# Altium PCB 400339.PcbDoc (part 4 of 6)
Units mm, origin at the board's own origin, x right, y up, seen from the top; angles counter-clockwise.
Board outline 146 x 63.5 mm, 4 copper layers (Top Layer, Mid-Layer 1, Mid-Layer 2, Bottom Layer), stack 1.505 mm thick; 400 components, 261 nets, 1523 pads, 1938 vias.
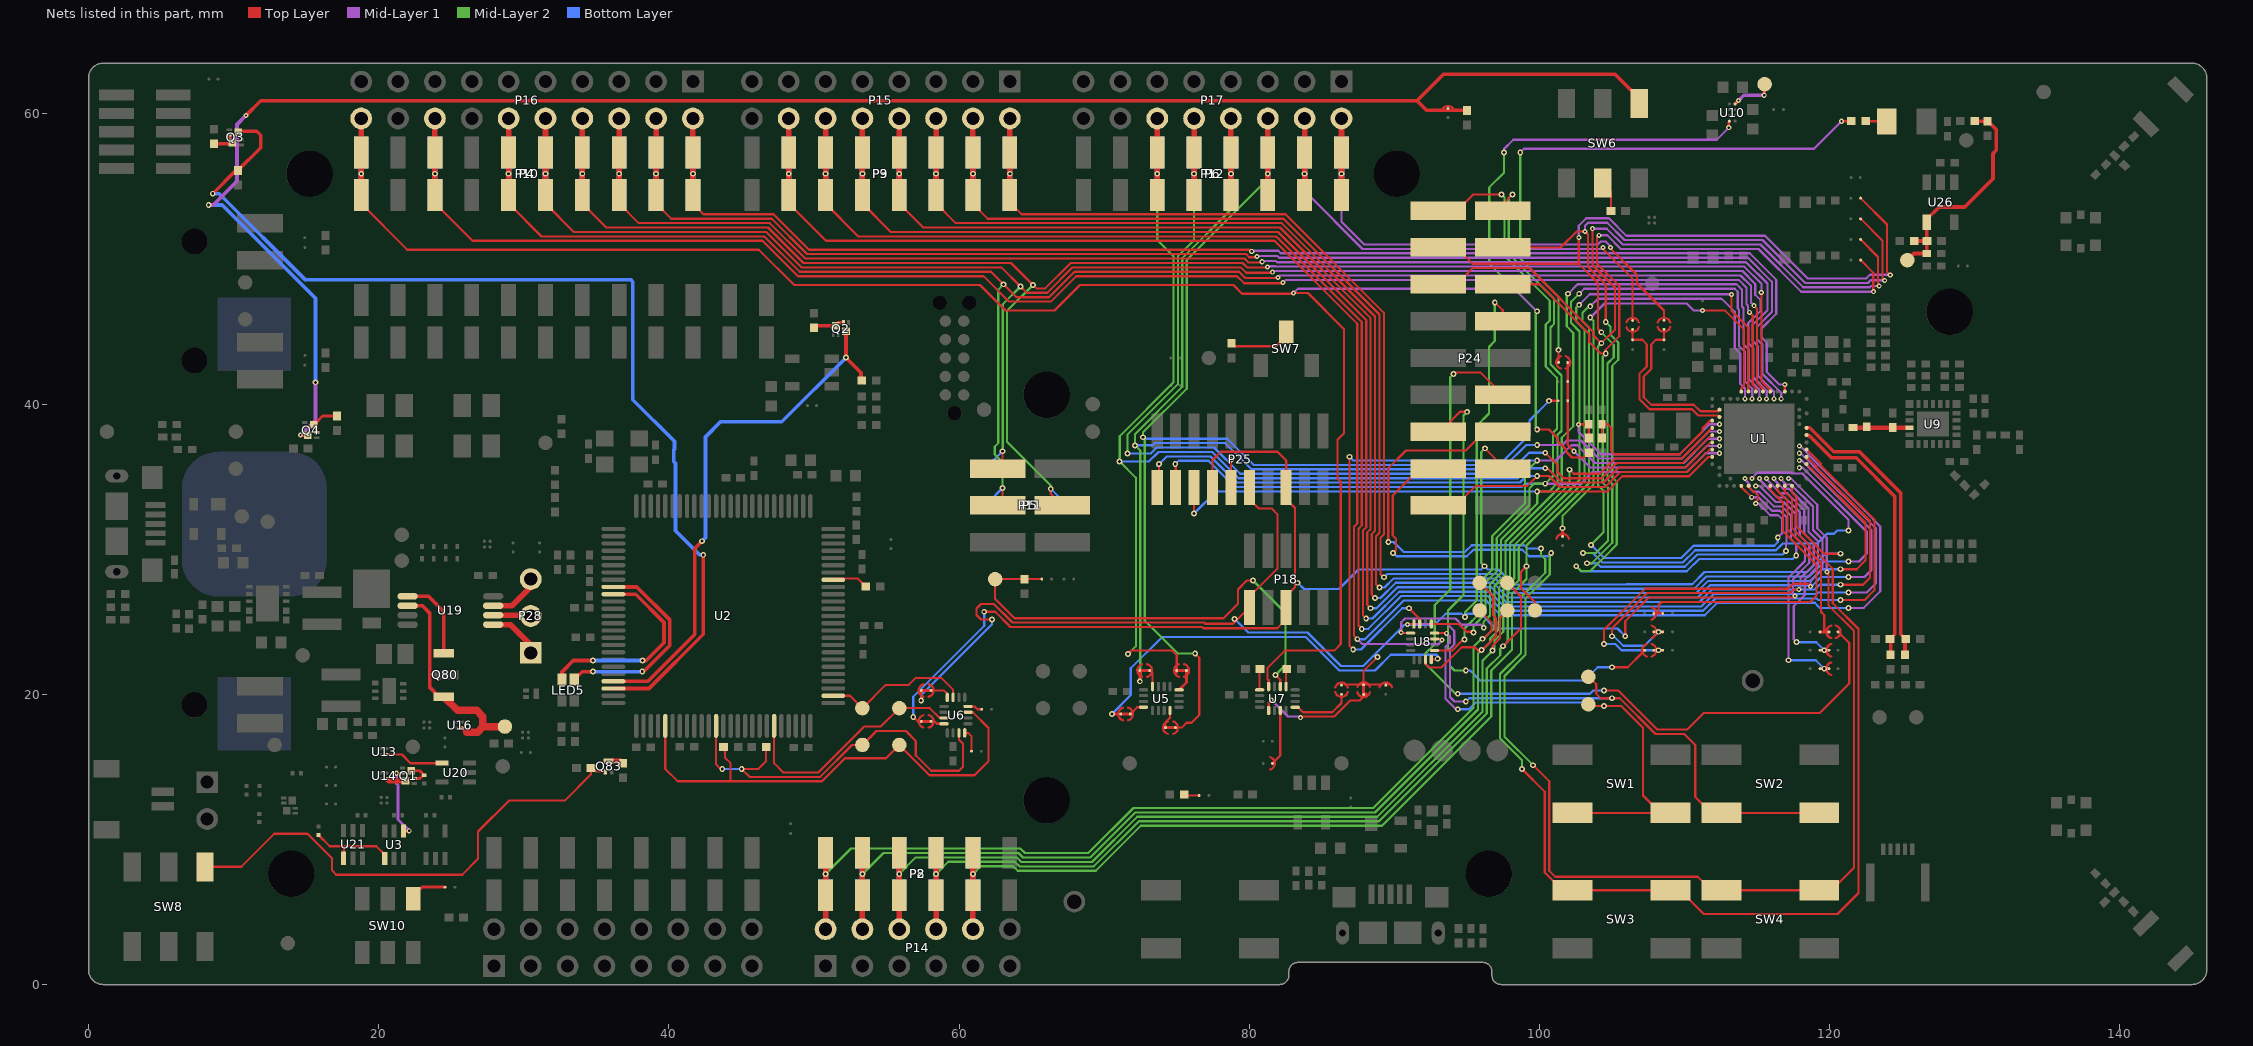
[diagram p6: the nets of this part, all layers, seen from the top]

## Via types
v1: diameter 0.4, hole 0.2, Top Layer to Bottom Layer, tented both sides, 1691 vias
v2: diameter 0.35, hole 0.15, Top Layer to Mid-Layer 1, tented both sides, 184 vias
v3: diameter 0.61, hole 0.305, Top Layer to Bottom Layer, 24 vias
v4: diameter 0.61, hole 0.305, Top Layer to Bottom Layer, tented both sides, 16 vias
v5: diameter 0.5, hole 0.3, Top Layer to Bottom Layer, tented both sides, 12 vias
v6: diameter 0.35, hole 0.15, Top Layer to Mid-Layer 1, tented top, 8 vias
v7: diameter 0.4, hole 0.2, Top Layer to Mid-Layer 1, tented top, 2 vias
v8: diameter 0.35, hole 0.15, Top Layer to Bottom Layer, tented top, 1 vias

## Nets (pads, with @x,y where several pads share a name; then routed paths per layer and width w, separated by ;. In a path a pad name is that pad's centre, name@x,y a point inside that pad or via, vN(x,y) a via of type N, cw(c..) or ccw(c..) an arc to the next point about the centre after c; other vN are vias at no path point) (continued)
NetP24_12: P24.12 SB25.2 | length 61.3
  Top Layer w0.152: v1(94.082,42.088) 94.183,42.189 95.923,42.189 P24.12@97.472,40.64 ; v1(104.445,20.269) 105.429,20.269 108.122,17.577 110.184,17.577 111.327,18.72 119.329,18.72 121.354,20.745 121.354,23.535 SB25.2@120.581,24.308
  Mid-Layer 2 w0.152: v1(94.082,42.088) 93.853,41.859 93.853,27.229 92.786,26.162 92.786,23.461 92.151,22.826 92.151,22.106 94.217,20.041 v1(94.369,20.041)
  Bottom Layer w0.152: v1(94.369,20.041) 103.484,20.041 103.712,20.269 v1(104.445,20.269)
NetP24_13: P24.13 SB20.2 | length 35.3
  Top Layer w0.152: P24.13@93.091,38.036 94.526,39.472 v1(95.021,39.472) ; v1(105.004,21.869) 106.088,21.869 107.108,22.889 SB20.2@107.257,23.038
  Mid-Layer 2 w0.152: v1(94.928,21.641) 94.148,21.641 93.836,21.953 93.836,22.938 93.701,23.073 93.701,25.782 94.767,26.849 94.767,39.218 v1(95.021,39.472)
  Bottom Layer w0.152: v1(94.928,21.641) 95.225,21.641 95.91,20.955 103.105,20.955 104.019,21.869 v1(105.004,21.869)
NetP28_1: P28.1 U19.5 | length 3.7
  Top Layer w0.381: U19.5@27.893,24.806 29.067,24.806 30.48,23.393 P28.1@30.48,22.86
NetP28_2: P28.2 U19.6 | length 2.6
  Top Layer w0.381: U19.6@27.893,25.456 30.424,25.456 P28.2@30.48,25.4
NetP28_3: P28.3 U19.7 | length 3.7
  Top Layer w0.381: U19.7@27.893,26.106 29.179,26.106 30.48,27.407 P28.3@30.48,27.94
NetQ1_2: Q1.2 U3.4 | length 5.1
  Top Layer w0.203: v2(21.227,14.561) Q1.2@21.64,14.561 ; U3.4@21.715,10.594 v6(22.102,10.594)
  Mid-Layer 1 w0.203: v2(21.227,14.561) 21.227,13.837 21.322,13.742 21.322,11.374 v6(22.102,10.594)
NetQ1_3: Q1.3 U14.A2 | length 1.2
  Top Layer w0.381: U14.A2@20.634,14.113 20.716,14.031 Q1.3@21.847,14.031
NetQ1_5: Q1.5 Q1.6 R6.2 | length 1.8
  Top Layer w0.203: Q1.6@22.247,14.731 22.822,14.731 R6.2@23.129,14.425 23.066,14.425 22.843,14.201 Q1.5@22.455,14.201
NetQ2_5: Q2.5 Q2.6 R22.2 | length 2.2
  Top Layer w0.254: R22.2@49.996,45.271 50.138,45.413 Q2.6@51.507,45.413 51.715,45.62 Q2.5@52.006,45.62
NetQ3_5: Q3.5 Q3.6 R24.2 | length 2.1
  Top Layer w0.254: R24.2@8.811,57.795 R24.2@8.661,57.945 9.831,57.945 Q3.6@9.919,58.034 9.712,58.241 Q3.5@9.712,58.5
NetQ4_3: Q4.3 R26.1 SB31.2 SW6.3 | length 130
  Top Layer w0.254: v2(10.844,59.893) 10.846,59.893 11.862,60.909 91.567,60.909 ; v2(14.617,37.867) Q4.3@15.116,37.867 ; R26.1@94.996,60.241 94.982,60.255 94.122,60.255 93.279,60.255 92.221,60.255 91.567,60.909 ; SW6.3@106.869,60.484 SW6.3@106.869,60.738 106.869,61.076 105.207,62.738 93.396,62.738 91.567,60.909
  Mid-Layer 1 w0.254: v1(8.28,53.721) 8.595,53.721 10.232,55.358 10.232,59.281 v2(10.844,59.893) ; v2(14.617,37.867) 15.646,38.896 v1(15.646,41.504)
  Bottom Layer w0.254: v1(8.28,53.721) 9.22,53.721 15.646,47.294 v1(15.646,41.504)
NetQ4_5: Q4.5 Q4.6 R41.2 | length 2.6
  Top Layer w0.152: R41.2@16.919,39.385 R41.2@17.12,39.184
  Top Layer w0.203: Q4.5@15.724,38.037 15.724,38.772 16.136,39.184 R41.2@17.12,39.184
NetQ80_1: Q80.1 U19.1 | length 5.6
  Top Layer w0.254: U19.1@22.196,26.756 23.434,26.756 24.489,25.701 Q80.1@24.489,22.836
NetQ80_3: Q80.3 TP34.1 U16.A1 U19.2 | length 15
  Top Layer w0.25: U16.A1@25.778,17.682 26.065,17.394
  Top Layer w0.254: U19.2@22.196,26.106 23.018,26.106 23.51,25.614 23.51,20.509 24.182,19.836 Q80.3@24.489,19.836
  Top Layer w0.508: Q80.3@24.489,19.836 25.427,18.898 26.746,18.898 27.178,18.466 27.178,17.755 ; 26.065,17.394 26.818,17.394 27.178,17.755 ; TP34.1@28.651,17.856 28.55,17.755 27.178,17.755
NetQ83_1: Q83.1 R94.1 SW8.4 | length 34.6
  Top Layer w0.152: SW8.4@8.028,8.109 10.522,8.109 12.802,10.389 15.088,10.389 16.789,8.687 16.789,7.851 17.071,7.569 25.756,7.569 26.851,8.664 26.851,10.544 28.981,12.675 32.817,12.675 34.638,14.495 R94.1@34.638,14.935 ; R94.1@34.714,14.961 34.988,14.687 Q83.1@35.614,14.687
NetQ83_3: Q83.3 R93.2 | length 1
  Top Layer w0.381: Q83.3@35.839,15.387 36.701,15.387 R93.2@36.83,15.257
NetR3_2: R3.2 SW6.5 | length 2.2
  Top Layer w0.152: SW6.5@104.369,55.238 104.935,54.671 R3.2@104.935,53.315
NetR4_2: R4.2 SW7.2 | length 4.4
  Top Layer w0.152: R4.2@78.791,44.188 78.985,43.994 81.84,43.994 82.55,44.704 SW7.2@82.55,44.965
NetR11_2: R11.2 R12.1 | length 1.4
  Top Layer w0.152: R11.2@122.498,59.5 123.907,59.5 R12.1@123.933,59.475
NetR18_2: R18.2 U3.1 U21.1 | length 6.2
  Top Layer w0.152: R18.2@15.85,10.307 16.627,9.53 17.603,9.53 ; U21.1@17.587,8.702 17.587,9.514 17.603,9.53 ; U3.1@20.415,8.694 20.415,8.956 19.841,9.53 17.603,9.53
NetR30_2: R30.2 U2.43 | length 2.5
  Top Layer w0.152: U2.43@51.329,27.9 51.42,27.991 53.008,27.991 R30.2@53.567,27.432
NetR49_1: R49.1 SB65.2 | length 1
  Top Layer w0.152: R49.1@75.532,13.081 75.582,13.03 SB65.2@76.548,13.03
NetR52_2: R52.2 U7.9 | length 1.2
  Top Layer w0.152: U7.9@82.54,20.535 R52.2@82.54,21.742
NetR53_2: R53.2 U7.13 | length 1.5
  Top Layer w0.152: U7.13@80.715,20.31 R53.2@80.715,21.768
NetR68_1: R68.1 SB33.2 TP19.1 U7.10 | length 33.2
  Top Layer w0.152: SB33.2@65.702,27.94 64.524,27.94 R68.1@64.516,27.932 64.508,27.94 TP19.1@62.484,27.94 62.484,26.594 63.828,25.25 78.234,25.25 79.223,26.238 79.223,27.229 79.832,27.838 v1(80.264,27.838) ; v1(81.813,21.336) 82.14,21.009 U7.10@82.14,20.535
  Mid-Layer 2 w0.152: v1(80.264,27.838) 82.499,25.604 82.499,22.021 v1(81.813,21.336)
NetSB16_2: SB16.2 U8.7 | length 36.5
  Top Layer w0.152: v1(86.919,36.371) 86.919,23.332 v1(87.163,23.088) ; v1(91.008,25.933) 91.748,25.194 U8.7@91.748,24.847 ; v1(100.672,40.231) SB16.2@101.276,40.231
  Bottom Layer w0.152: v1(86.919,36.371) 87.173,36.117 97.548,36.117 99.314,37.884 99.314,38.873 v1(100.672,40.231) ; v1(87.163,23.088) 87.705,23.088 90.551,25.933 v1(91.008,25.933)
NetSB42_1: SB42.1 U7.1 | length 8.6
  Top Layer w0.152: U7.1@81.34,18.885 81.34,19.415 v2(81.534,19.609) ; v2(83.541,18.39) 83.617,18.466 85.851,18.466 86.965,19.58 87.608,19.58 88.087,20.058
  Mid-Layer 1 w0.152: v2(81.534,19.609) 82.677,18.466 83.464,18.466 v2(83.541,18.39)
NetSB45_1: SB45.1 U7.5 | length 4.2
  Top Layer w0.152: U7.5@83.165,19.11 83.361,19.11 83.701,18.771 85.725,18.771 86.36,19.406 86.36,19.833 SB45.1@86.36,20.008
NetSB46_1: SB46.1 U7.3 | length 3.9
  Top Layer w0.152: SB46.1@81.592,15.24 81.741,15.389 82.14,15.788 U7.3@82.14,18.885
NetSB50_1: SB50.1 U8.16 | length 28.9
  Top Layer w0.152: U8.16@92.548,22.397 v1@92.907,22.397 ; v1@93.04,22.53 v1@92.907,22.397 ; v1@93.167,22.479 93.085,22.397 v1@92.907,22.397
  Top Layer w0.203: v1(70.536,18.644) 70.963,18.644 SB50.1@71.138,18.644
  Bottom Layer w0.152: v1(70.536,18.644) 71.839,19.947 71.839,21.794 73.998,23.952 83.887,23.952 86.199,21.641 88.664,21.641 89.756,22.733 92.913,22.733 v1@93.167,22.479
  other v1: 92.989,22.454
NetSB50_2: SB50.2 U5.16 | length 1.1
  Top Layer w0.152: SB50.2@71.813,18.644 72.28,19.11 U5.16@72.714,19.11
NetSB51_2: SB51.2 U5.4 | length 1.3
  Top Layer w0.152: SB51.2@74.237,17.704 74.237,18.077 74.539,18.38 U5.4@74.539,18.885
NetSB52_2: SB52.2 U5.8 | length 1.6
  Top Layer w0.152: U5.8@75.157,20.307 U5.8@75.164,20.314
  Top Layer w0.203: U5.8@75.164,20.31 75.164,20.314 75.674,20.824 SB52.2@75.674,21.641
NetSB53_2: SB53.2 U5.12 | length 1.2
  Top Layer w0.152: SB53.2@73.134,21.641 73.332,21.443 U5.12@73.332,20.532
NetSB54_2: SB54.2 U6.16 | length 1.6
  Top Layer w0.152: U6.16@60.392,17.342 60.628,17.342 60.851,17.119 SB54.2@60.851,16.078
NetSB55_2: SB55.2 U6.4 | length 1
  Top Layer w0.152: U6.4@60.617,19.167 61.071,19.167 61.265,18.974 SB55.2@61.562,18.974
NetSB56_2: SB56.2 U6.8 | length 1.5
  Top Layer w0.152: SB56.2@58.072,20.269 58.953,20.269 59.192,20.031 U6.8@59.192,19.792
NetSB57_2: SB57.2 U6.12 | length 1
  Top Layer w0.152: SB57.2@58.072,18.136 58.318,18.136 58.487,17.967 U6.12@58.967,17.967 U6.12@58.967,17.937
NetSB58_2: SB58.2 SW10.1 | length 2.6
  Top Layer w0.203: SW10.1@22.375,5.914 22.375,6.093 22.987,6.706 SB58.2@24.58,6.706
NetSW1_2: SW1.2 TP20.1 U8.4 | length 35.3
  Top Layer w0.152: U8.4@92.773,24.222 93.609,24.222 v2@93.624,24.206 ; SW1.2@102.278,11.83 SW1.2@108.331,11.83 ; TP20.1@103.378,19.304 103.48,19.202 v1(104.445,19.202) 105.634,19.202 107.137,17.699 107.137,13.024 SW1.2@108.331,11.83 ; SW1.2@109.707,11.83 SW1.2@109.028,11.83 SW1.2@108.331,11.83
  Mid-Layer 1 w0.152: v2@93.624,24.206 93.828,24.003 93.828,23.562 93.531,23.266 93.531,19.693 94.251,18.974 v1(94.369,18.974)
  Bottom Layer w0.152: v1(94.369,18.974) 95.149,18.974 95.606,19.431 103.454,19.431 103.683,19.202 v1(104.445,19.202)
  other v2: 93.599,24.206
NetSW2_2: SW2.2 TP21.1 U8.8 | length 42.9
  Top Layer w0.152: v2@90.887,24.847 U8.8@91.348,24.847 ; TP21.1@103.378,21.234 103.914,20.699 103.914,20.049 104.227,19.736 v1(105.004,19.736) 105.532,19.736 107.995,17.272 109.981,17.272 110.744,16.509 110.744,12.927 111.841,11.83 SW2.2@112.54,11.83 SW2.2@119.29,11.83 SW2.2@119.913,11.83
  Mid-Layer 1 w0.152: v2@90.887,24.847 93.645,24.847 94.132,24.359 94.132,23.436 93.836,23.139 93.836,19.82 94.148,19.507 v1(94.928,19.507)
  Bottom Layer w0.152: v1(94.928,19.507) 95.157,19.736 v1(105.004,19.736)
  other v2: 90.912,24.822
NetTP50_1: TP50.1 U10.A2 | length 3.2
  Top Layer w0.152: TP50.1@115.519,62.052 TP50.1@115.656,62.189
  Top Layer w0.254: U10.A2@113.497,60.7 v2(113.715,60.918) ; v2(115.494,61.29) TP50.1@115.494,62.012
  Mid-Layer 1 w0.254: v2(113.715,60.918) 114.087,61.29 v2(115.494,61.29)
NetU13_B2: U13.B2 U20.4 | length 3.7
  Top Layer w0.152: U13.B2@20.571,15.853 21.6,15.853 22.197,15.255 U20.4@24.018,15.255
OB_LED1: LED5.4 U2.84 | length 14.1
  Top Layer w0.254: LED5.4@33.486,21.02 34.031,21.565 v1(34.763,21.565) ; U2.84@36.179,27.4 37.792,27.4 40.071,25.121 40.071,23.38 38.256,21.565 v1(38.166,21.565)
  Bottom Layer w0.254: v1(34.763,21.565) v1(38.166,21.565)
OB_LED2: LED5.3 U2.85 | length 14.1
  Top Layer w0.254: LED5.3@32.636,21.02 32.636,21.546 33.416,22.327 v1(34.763,22.327) ; U2.85@36.179,26.9 37.717,26.9 39.665,24.952 39.665,23.548 38.443,22.327 v1(38.192,22.327)
  Bottom Layer w0.254: v1(34.763,22.327) v1(38.192,22.327)
OB_RESET: TP7.1 U2.27 U6.7 | length 10.3
  Top Layer w0.152: U2.27@51.329,19.9 52.49,19.9 TP7.1@53.34,19.05 54.94,20.65 56.54,20.65 57.023,21.133 58.776,21.133 59.592,20.317 U6.7@59.592,19.792
OB_SWDCLK: R28.2 TP6.1 U2.5 U6.3 | length 34.6
  Top Layer w0.152: U2.5@39.754,17.825 39.754,14.856 40.604,14.006 44.256,14.006 ; R28.2@43.772,16.358 43.875,16.255 43.875,15.621 44.256,15.24 44.256,14.006 ; U6.3@60.617,18.767 60.938,18.767 62.027,17.678 62.027,15.392 61.062,14.427 57.963,14.427 TP6.1@55.88,16.51 54.966,15.596 52.145,15.596 50.555,14.006 44.256,14.006
OB_SWDIO: R29.2 TP5.1 U2.12 U6.15 | length 28.5
  Top Layer w0.152: U2.12@43.254,17.825 43.244,17.814 43.244,15.176 43.576,14.844 v1(43.678,14.844) ; R29.2@46.703,16.358 46.703,15.41 46.137,14.844 v1(45.018,14.844) 45.551,14.31 50.428,14.31 52.628,16.51 TP5.1@53.34,16.51 54.305,17.475 56.337,17.475 57.023,16.789 57.023,15.798 58.089,14.732 59.995,14.732 60.274,15.011 60.274,16.588 59.992,16.87 U6.15@59.992,17.342
  Bottom Layer w0.152: v1(43.678,14.844) v1(45.018,14.844)
OB_SWO: TP8.1 U2.20 U6.11 | length 16.7
  Top Layer w0.152: U2.20@47.254,17.825 47.254,15.24 47.879,14.615 50.302,14.615 53.467,17.78 54.61,17.78 TP8.1@55.88,19.05 57.983,19.05 58.665,18.367 U6.11@58.967,18.367
P0.00: P6.1 P12.1 P17.2 SB4.2 | length 37.6
  Top Layer w0.152: v2@104.851,50.775 106.723,48.902 106.723,48.318 108.585,46.457 108.585,45.953 SB4.2@108.585,45.778
  Top Layer w0.381: P6.1@86.36,54.415 v1(86.36,55.88) P6.1@86.36,57.345 P17.2@86.36,59.69
  Mid-Layer 1 w0.152: v1(86.36,55.88) 86.36,52.577 87.934,51.003 104.026,51.003 104.227,51.204 104.578,51.204 104.902,50.879 v2(104.902,50.8) ; v2@104.851,50.775 v2@104.851,50.8
  Bottom Layer w0.381: P12.1@86.36,54.415 v1(86.36,55.88) P12.1@86.36,57.345
P0.00/XL1: SB2.2 SB4.1 U1.D2 | length 11.2
  Top Layer w0.145: 111.1,39.512 112.309,39.512 U1.D2@112.414,39.617
  Top Layer w0.152: SB4.1@108.585,45.154 108.585,44.432 108.029,44.432 107.703,44.107 107.703,42.418 107.195,41.91 107.195,40.479 107.716,39.958 110.642,39.958 111.077,39.523
P0.01: P6.2 P12.2 P17.4 SB3.2 | length 37.4
  Top Layer w0.152: v2(104.394,50.8) 104.394,50.673 106.426,48.641 106.426,45.953 SB3.2@106.426,45.778
  Top Layer w0.381: P6.2@83.82,54.415 v1(83.82,55.88) P6.2@83.82,57.345 P17.4@83.82,59.69
  Mid-Layer 1 w0.152: v1(83.82,55.88) 83.82,54.686 87.808,50.698 v2@104.318,50.698
  Bottom Layer w0.381: P12.2@83.82,54.415 v1(83.82,55.88) P12.2@83.82,57.345
P0.01/XL2: SB1.2 SB3.1 U1.F2 | length 11.9
  Top Layer w0.145: 110.922,39.222 112.309,39.222 U1.F2@112.414,39.117
  Top Layer w0.152: SB3.1@106.426,45.154 SB1.2@106.426,44.432 107.086,44.432 107.399,44.12 107.399,42.596 106.891,42.088 106.891,40.353 107.59,39.654 110.516,39.654 110.922,39.248 110.922,39.222
P0.02/AIN0: P4.8 P10.8 P16.16 U1.A12 | length 111.2
  Top Layer w0.152: P4.8@23.876,54.415 23.876,53.848 26.467,51.257 46.455,51.257 48.894,48.819 61.694,48.819 63.447,47.066 66.326,47.066 68.079,48.819 79.164,48.819 79.65,48.332 82.289,48.332 v2(82.333,48.376) ; v2(114.478,46.33) 114.702,46.106 114.702,41.33 114.914,41.119 U1.A12@114.914,40.867
  Top Layer w0.381: P4.8@23.876,54.415 v1(23.876,55.88) P4.8@23.876,57.345 P16.16@23.876,59.69
  Mid-Layer 1 w0.152: v2(82.333,48.376) 82.522,48.565 113.741,48.565 114.275,48.031 114.275,46.886 114.374,46.786 114.374,46.434 v2(114.478,46.33)
  Bottom Layer w0.381: P10.8@23.876,53.848 v1(23.876,55.88) P10.8@23.876,57.345
P0.03/AIN1: P2.1 P8.1 P14.2 TP42.1 U1.B13 | length 113.2
  Top Layer w0.152: TP42.1@95.885,25.781 96.69,24.976 96.69,24.369 96.146,23.825 v1(96.081,23.825)
  Top Layer w0.381: P14.2@50.8,3.81 P2.1@50.8,6.155 v1(50.8,7.62) P2.1@50.8,9.085
  Mid-Layer 1 w0.152: v1(101.981,47.607) 102.631,48.258 113.592,48.258 113.97,47.88 113.97,46.724 114.071,46.622 114.071,44.119 114.456,43.735 114.456,41.706 115.164,40.998 v2(115.164,40.367)
  Mid-Layer 2 w0.152: v1(50.8,7.62) 52.553,9.373 64.226,9.373 64.541,9.057 68.912,9.057 72.021,12.167 88.544,12.167 95.462,19.084 95.462,23.275 95.974,23.787 96.119,23.787 96.901,24.569 96.901,27.467 97.663,28.229 97.663,30.532 101.244,34.113 101.244,34.116 101.542,34.414 101.542,37.68 102.337,38.474 102.337,44.905 101.879,45.363 101.879,47.506 v1(101.981,47.607)
  Bottom Layer w0.381: P8.1@50.8,6.155 v1(50.8,7.62) P8.1@50.8,9.677
P0.04/AIN2: P2.2 P8.2 P14.4 TP43.1 U1.J1 U8.15 | length 96.4
  Top Layer w0.15: U1.J1@111.86,38.319 U1.J1@111.908,38.367
  Top Layer w0.152: U8.15@92.148,22.397 92.148,22.101 92.406,21.843 93.243,21.843 94.64,23.241 95.555,23.241 v1@95.872,22.924 ; TP43.1@95.885,27.686 96.825,26.746 96.825,25.425 96.988,25.262 96.988,23.989 v1@96.037,23.038 ; v1(102.083,35.484) 102.362,35.204 104.168,35.204 105.209,36.246 109.8,36.246 109.979,36.424 109.979,36.426 111.547,37.995 111.547,38.019 111.762,38.233 111.786,38.233 111.86,38.307 U1.J1@111.86,38.319 ; U1.J1@111.908,38.367 U1.J1@111.914,38.367
  Top Layer w0.381: P14.4@53.34,3.81 P2.2@53.34,6.155 v1(53.34,7.62) P2.2@53.34,9.085
  Mid-Layer 2 w0.152: v1(53.34,7.62) 54.788,9.068 64.1,9.068 64.415,8.753 69.038,8.753 72.147,11.862 73.33,11.862 88.671,11.862 95.766,18.957 95.766,22.818 v1(96.012,23.063) ; v1@96.041,23.034 96.612,23.606 96.612,23.853 97.203,24.444 97.203,25.017 97.206,25.019 97.206,27.341 97.968,28.103 97.968,30.405 102.083,34.52 v1(102.083,35.484)
  Bottom Layer w0.381: P8.2@53.34,6.155 v1(53.34,7.62) P8.2@53.34,9.085
P0.05/AIN3: P6.3 P12.3 P17.6 SB51.1 U1.K2 | length 95.7
  Top Layer w0.152: SB51.1@74.912,17.704 75.087,17.704 75.342,17.704 75.672,18.034 76.022,18.034 76.558,18.569 76.558,22.528 v1(76.276,22.809)
  Top Layer w0.381: P6.3@81.28,54.661 v1(81.28,55.88) P6.3@81.28,57.345 P17.6@81.28,59.69
  Mid-Layer 1 w0.152: v1(99.847,37.186) 101.589,37.186 101.893,37.49 102.87,37.49 104.115,36.246 109.8,36.246 111.672,38.117 v2(112.414,38.117)
  Mid-Layer 2 w0.152: v1(76.276,22.809) 75.082,22.809 72.796,25.095 72.796,37.592 v1(72.669,37.719) 72.669,38.042 75.692,41.065 75.692,49.936 81.28,55.524 v1(81.28,55.88)
  Bottom Layer w0.152: v1(72.669,37.719) 72.771,37.617 78.486,37.617 80.289,35.814 97.721,35.814 99.093,37.186 v1(99.847,37.186)
  Bottom Layer w0.381: P12.3@81.28,54.415 v1(81.28,55.88) P12.3@81.28,57.345
P0.06: P6.4 P12.4 P17.8 SB53.1 U1.L1 | length 90.1
  Top Layer w0.15: 109.804,35.941 109.925,35.941 110.282,36.299 110.282,36.3 111.85,37.867 U1.L1@111.914,37.867
  Top Layer w0.152: v1(100.406,36.652) 101.244,35.814 101.244,35.33 101.675,34.9 104.294,34.9 105.335,35.941 109.804,35.941
  Top Layer w0.203: v1(72.459,20.897) 72.459,21.288 SB53.1@72.459,21.641
  Top Layer w0.381: P6.4@78.74,54.415 v1(78.74,55.88) P6.4@78.74,57.345 P17.8@78.74,59.69
  Mid-Layer 2 w0.152: v1(72.459,20.897) 72.492,20.93 72.492,36.805 v1(72.136,37.16) 72.136,37.94 75.387,41.191 75.387,50.063 78.74,53.415 v1(78.74,55.88)
  Bottom Layer w0.152: v1(72.136,37.16) 73.339,37.16 73.491,37.313 78.351,37.313 80.155,35.509 98.146,35.509 99.289,36.652 v1(100.406,36.652)
  Bottom Layer w0.381: P12.4@78.74,54.415 v1(78.74,55.88) P12.4@78.74,57.345
P0.07: P6.5 P12.5 P17.10 P25.12 U1.M2 U8.1 | length 91.7
  Top Layer w0.152: P25.12@78.74,34.245 v1(78.74,36.17) ; U8.1@92.773,23.022 93.99,23.022 94.743,23.774 v1(94.844,23.774)
  Top Layer w0.381: P6.5@76.2,54.61 v1(76.2,55.88) P6.5@76.2,57.345 P17.10@76.2,59.69
  Mid-Layer 1 w0.152: v1(99.847,36.119) 101.151,36.119 102.203,37.17 102.606,37.17 103.835,35.941 109.927,35.941 111.603,37.617 v2(112.414,37.617)
  Mid-Layer 2 w0.152: v1(71.603,36.601) 71.603,37.897 75.082,41.377 75.082,50.189 76.2,51.306 v1(76.2,55.88) ; v1(94.844,23.774) 94.844,24.544 95.987,25.687 95.987,27.846 96.749,28.608 96.749,30.91 99.009,33.171 99.009,35.281 v1(99.847,36.119)
  Bottom Layer w0.152: v1(71.603,36.601) 73.211,36.601 73.618,37.008 77.579,37.008 79.382,35.204 98.347,35.204 99.261,36.119 v1(99.847,36.119)
  Bottom Layer w0.381: P12.5@76.2,54.415 v1(76.2,55.88) P12.5@76.2,57.345
P0.08: P6.6 P12.6 P17.12 SB52.1 U1.N1 | length 92.2
  Top Layer w0.15: 110.082,35.636 111.814,37.367 U1.N1@111.914,37.367
  Top Layer w0.152: v1(71.653,22.784) 71.884,23.014 74.7,23.014 74.999,22.716 74.999,21.463 ; v1(100.406,35.585) 100.558,35.585 101.548,34.595 104.42,34.595 105.462,35.636 110.082,35.636
  Top Layer w0.381: P6.6@73.66,54.712 v1(73.66,55.88) P6.6@73.66,57.345 P17.12@73.66,59.69
  Mid-Layer 2 w0.152: v1(71.653,22.784) 72.187,23.317 72.187,34.925 v1(71.069,36.043) 71.069,37.794 74.778,41.503 74.778,50.19 73.66,51.308 v1(73.66,55.88)
  Bottom Layer w0.152: v1(71.069,36.043) 73.083,36.043 73.744,36.703 77.452,36.703 79.256,34.9 98.527,34.9 99.212,35.585 v1(100.406,35.585)
  Bottom Layer w0.381: P12.6@73.66,54.415 v1(73.66,55.88) P12.6@73.66,57.345
P0.09/NFC1: R43.2 R44.2 U1.L24 | length 19
  Top Layer w0.25: U1.L24@118.414,37.867 118.569,37.867 118.569,37.782 118.655,37.782 120.125,36.311 121.829,36.311 124.5,33.64 124.5,24.131 R43.2@124.169,23.8 124.206,23.762 R44.2@124.206,22.725
P0.10/NFC2: R45.2 R46.2 U1.J24 | length 19.6
  Top Layer w0.25: U1.J24@118.414,38.367 118.638,38.367 120.292,36.714 122.062,36.714 124.903,33.873 124.903,24.149 R45.2@125.251,23.8 ; R46.2@125.197,22.725 R45.2@125.197,23.745
P0.11: P24.1 P25.18 U1.T2 U8.5 | length 83.8
  Top Layer w0.152: v1(74.905,35.865) 74.93,35.839 P25.18@74.93,34.245 ; U8.5@92.548,24.847 94.437,24.847 94.976,24.308 95.402,24.308 v1(95.453,24.257) ; P24.1@93.027,53.34 94.336,53.34 95.453,54.458 v1(97.384,54.458)
  Mid-Layer 1 w0.152: v1(100.406,34.519) 102.84,34.519 103.653,35.331 110.179,35.331 111.465,36.617 v2(112.414,36.617)
  Mid-Layer 2 w0.152: v1(95.453,24.257) 95.453,24.714 96.291,25.552 96.291,27.72 97.053,28.482 97.053,30.784 99.314,33.045 99.314,34.206 99.626,34.519 v1(100.406,34.519) 100.937,35.05 100.937,38.021 101.203,38.287 101.203,41.824 100.432,42.596 100.432,45.491 100.711,45.771 100.711,47.117 97.587,50.241 97.587,54.254 v1(97.384,54.458)
  Bottom Layer w0.152: v1(74.905,35.865) 75.133,36.093 77.2,36.093 79.003,34.29 98.784,34.29 99.012,34.519 v1(100.406,34.519)
P0.12: P24.2 P25.16 U1.U1 U8.9 | length 82.4
  Top Layer w0.15: 110.16,35.027 110.315,35.027 111.656,36.367 U1.U1@111.914,36.367
  Top Layer w0.152: v1(76.2,32.461) P25.16@76.2,34.245 ; v2(90.475,24.257) 90.51,24.222 U8.9@91.123,24.222 ; P24.2@97.472,53.34 97.472,53.784 v1(98.146,54.458) ; v1(99.847,33.985) 104.673,33.985 105.714,35.027 110.16,35.027
  Mid-Layer 1 w0.152: v2(90.475,24.257) 90.475,24.97 90.73,25.226 94.213,25.226 94.648,24.79 95.961,24.79 v1(96.164,24.587)
  Mid-Layer 2 w0.152: v1@96.139,24.587 96.139,24.969 96.596,25.426 96.596,27.594 97.358,28.356 97.358,30.658 99.847,33.147 v1(99.847,33.985) 100.686,33.985 101.24,34.539 101.24,37.867 101.524,38.151 101.524,41.981 100.762,42.743 100.762,45.288 101.016,45.542 101.016,47.25 97.892,50.374 97.892,54.204 v1(98.146,54.458)
  Bottom Layer w0.152: v1(76.2,32.461) 77.724,33.985 v1(99.847,33.985)
P0.13: P24.3 SB5.1 U1.AD8 | length 85.5
  Top Layer w0.152: P24.3@93.497,50.8 94.285,50.8 95.402,49.682 102.718,49.682 ; v2(102.718,51.486) 102.718,49.682 ; v1(104.267,44.958) 104.046,45.179 104.046,48.354 102.718,49.682 ; U1.AD8@113.914,34.367 113.914,34.295 v2(114.63,33.579) ; SB5.1@122.139,54.197 123.952,52.384 123.952,49.124 v2(124.181,48.895)
  Mid-Layer 1 w0.152: v2(102.718,51.486) 102.718,52.299 103.226,52.807 104.8,52.807 105.994,51.613 115.545,51.613 118.498,48.659 122.522,48.659 122.778,48.915 124.16,48.915 v2(124.181,48.895) ; v2(114.63,33.579) 115.102,33.579 116.03,32.651 116.578,32.651 117.041,32.188 117.041,30.427 116.992,30.378 v1(116.992,29.87)
  Mid-Layer 2 w0.152: v1(103.276,29.032) 103.607,29.032 105.022,30.447 105.022,34.493 104.699,34.816 104.699,42.799 105.131,43.231 105.131,44.087 104.267,44.95 v1(104.267,44.958)
  Bottom Layer w0.152: v1(103.276,29.032) 103.97,29.032 104.211,28.792 110.022,28.792 110.402,29.171 110.419,29.171 110.882,29.635 116.757,29.635 v1(116.992,29.87)
P0.14: P24.4 SB6.1 U1.AC9 | length 83.6
  Top Layer w0.152: P24.4@97.472,50.8 101.461,50.8 102.553,51.892 v2(103.149,51.892) 103.353,51.689 103.353,49.468 104.572,48.249 v1(104.572,45.669) ; SB6.1@122.139,52.774 123.647,51.266 123.647,48.666 v2(123.8,48.514)
  Mid-Layer 1 w0.152: v2(103.149,51.892) 103.149,52.299 103.352,52.502 104.674,52.502 105.868,51.308 115.372,51.308 118.323,48.357 122.647,48.357 122.825,48.534 123.779,48.534 v2(123.8,48.514) ; v2(114.164,34.867) 114.164,34.8 114.512,34.451 114.512,34.201 114.747,33.966 115.142,33.966 116.155,32.953 116.703,32.953 117.343,32.313 117.343,30.699 117.704,30.338 v1(117.704,29.566)
  Mid-Layer 2 w0.152: v1(102.54,28.829) 102.868,28.501 103.507,28.501 104.978,29.972 104.978,29.976 105.324,30.322 105.324,34.655 105.022,34.958 105.022,42.639 105.435,43.053 105.435,44.247 104.902,44.78 104.902,45.339 v1(104.572,45.669)
  Bottom Layer w0.152: v1(102.54,28.829) 102.88,28.489 110.164,28.489 111.008,29.333 117.471,29.333 v1(117.704,29.566)
P0.15: P24.5 SB7.1 U1.AD10 | length 81.9
  Top Layer w0.152: P24.5@93.027,48.26 94.285,48.26 95.402,49.378 99.314,49.378 103.734,44.958 103.734,44.737 104.267,44.204 v1(104.267,44.196) 105.207,45.136 105.207,48.034 103.657,49.584 v2(103.657,52.095) ; U1.AD10@114.414,34.367 114.414,34.3 114.747,33.966 114.81,33.966 115.062,33.714 115.062,33.435 114.91,33.282 v2(114.91,33.147) ; SB7.1@122.139,51.352 123.342,50.149 123.342,48.209 v2(123.419,48.133)
  Mid-Layer 1 w0.152: v2(103.657,52.095) 104.649,52.095 105.742,51.003 115.233,51.003 118.182,48.054 122.773,48.054 122.871,48.153 123.398,48.153 v2(123.419,48.133) ; v2(114.91,33.147) 115.106,33.147 115.905,32.348 116.452,32.348 116.738,32.063 116.738,31.115 v1(116.434,30.81)
  Mid-Layer 2 w0.152: v1(103.556,30.302) 104.417,31.163 104.417,34.038 104.041,34.415 104.041,43.97 v1(104.267,44.196)
  Bottom Layer w0.152: v1(103.556,30.302) 104.462,29.396 109.772,29.396 110.615,30.24 116.183,30.24 116.434,30.49 v1(116.434,30.81)
P0.16: P24.6 SB8.1 U1.AC11 | length 85.4
  Top Layer w0.152: P24.6@97.472,48.26 100.011,48.26 103.429,44.842 103.429,44.28 104.224,43.485 v1(104.572,43.485) 104.572,43.746 105.504,44.679 105.504,48.158 103.962,49.7 103.962,51.486 v2(104.115,51.638) ; SB8.1@122.139,49.93 123.015,49.054 123.015,47.775 v2(123.038,47.752)
  Mid-Layer 1 w0.152: v2(104.115,51.638) 104.676,51.638 105.615,50.698 115.097,50.698 118.043,47.752 v2(123.038,47.752) ; v2(114.664,34.867) 114.664,34.935 114.997,35.269 117.33,35.269 117.382,35.216 118.128,35.216 118.277,35.067 121.31,32.034 v1(121.31,31.293)
  Mid-Layer 2 w0.152: v1(102.997,29.743) 103.89,29.743 104.719,30.573 104.719,34.239 104.369,34.59 104.369,43.282 v1(104.572,43.485)
  Bottom Layer w0.152: v1(102.997,29.743) 103.687,29.743 104.336,29.094 109.897,29.094 110.74,29.937 116.308,29.937 116.772,30.401 119.157,30.401 119.817,31.062 120.3,31.062 120.531,31.293 v1(121.31,31.293)
P0.17: SB13.1 SB23.1 U1.AD12 | length 17.7
  Top Layer w0.203: SB13.1@119.337,21.768 v1(119.634,21.768) 119.782,21.768 SB23.1@119.957,21.768
  Mid-Layer 1 w0.152: v2(114.914,34.367) 115.169,34.367 116.28,33.256 116.828,33.256 117.646,32.438 117.646,30.824 118.3,30.17 118.3,29.189 117.178,28.067 117.178,22.36 v1(117.17,22.352)
  Bottom Layer w0.152: v1(117.17,22.352) 119.05,22.352 v1(119.634,21.768)
P0.18/RESET: P18.10 P24.8 P25.10 SB42.2 SB44.2 SB45.2 SB56.1 U1.AC13 | length 124
  Top Layer w0.152: v1(57.389,19.583) 57.396,19.591 57.396,19.916 ; v1(62.272,25.155) 61.517,25.155 61.199,25.473 61.199,25.915 61.512,26.227 62.395,26.227 63.678,24.945 76.877,24.945 76.963,24.858 78.878,24.858 P18.10@80.01,25.99 80.01,26.717 81.94,28.647 81.94,32.41 81.534,32.816 80.645,32.816 80.01,33.452 P25.10@80.01,34.245 ; 86.589,20.683 86.668,20.683 SB42.2@87.884,20.683 ; v1(88.849,22.581) 87.884,21.615 SB42.2@87.884,20.683 ; 89.1,20.683 SB42.2@87.884,20.683 ; SB44.2@89.408,20.683 89.716,20.683 ; v1(96.926,47.015) 97.472,46.469 P24.8@97.472,45.72 ; v1(105.918,24.003) 105.918,25.044 107.544,26.67 117.526,26.67 v2(117.627,26.772)
  Top Layer w0.203: 57.396,19.916 SB56.1@57.396,20.269
  Mid-Layer 1 w0.152: v2(115.164,34.867) 115.164,34.8 116.406,33.558 116.954,33.558 117.948,32.564 117.948,30.949 118.602,30.295 118.602,29.063 117.48,27.941 117.48,26.919 v2(117.627,26.772)
  Mid-Layer 2 w0.152: v1(94.869,25.324) 94.869,25.658 95.682,26.471 95.682,38.516 96.52,39.354 96.52,43.942 96.926,44.348 v1(96.926,47.015)
  Bottom Layer w0.152: v1(57.389,19.583) 57.389,19.949 62.272,24.832 v1(62.272,25.155) ; v1(78.994,25.197) 79.934,24.257 84.01,24.257 86.322,21.946 87.856,21.946 88.67,22.76 ; v1(88.849,22.581) 88.67,22.76 ; v1(94.869,25.324) 94.64,25.552 93.539,25.552 92.774,24.787 90.697,24.787 88.67,22.76 ; 94.869,25.552 95.95,25.552 96.964,24.539 105.382,24.539 v1(105.918,24.003)
P0.19: SB11.1 SB21.1 U1.AC15 | length 28.7
  Top Layer w0.152: v1(105.004,24.003) 105.004,24.562 107.417,26.975 117.263,26.975 117.504,27.216 v2(117.881,27.216)
  Top Layer w0.203: SB21.1@107.881,24.308 108.056,24.308 v1(108.204,24.308) SB11.1@108.501,24.308
  Mid-Layer 1 w0.152: v2(115.664,34.867) 115.664,34.8 116.603,33.86 117.079,33.86 118.25,32.689 118.25,31.074 118.905,30.42 118.905,28.938 117.991,28.024 117.991,27.325 v2(117.881,27.216)
  Bottom Layer w0.152: v1(105.004,24.003) 105.122,24.003 105.783,23.343 107.239,23.343 v1(108.204,24.308)
P0.20: SB12.1 SB22.1 U1.AD16 | length 21.3
  Top Layer w0.152: SB22.1@107.881,25.578 108.204,25.578 ; SB12.1@108.501,25.578 108.204,25.578 ; U1.AD16@115.914,34.367 115.914,34.099 116.792,33.221 116.792,32.004 116.794,32.002 116.794,31.234 119.108,28.92 119.108,26.805 118.669,26.365 108.41,26.365 108.204,26.16 108.204,25.578
P0.21: SB14.1 SB24.1 U1.AC17 | length 16.3
  Top Layer w0.203: SB14.1@119.337,23.038 v1(119.634,23.038) 119.782,23.038 SB24.1@119.957,23.038
  Mid-Layer 1 w0.152: v2(116.164,34.867) 116.164,34.8 116.801,34.163 117.204,34.163 118.553,32.814 118.553,31.2 119.207,30.545 119.207,28.813 118.293,27.899 118.293,26.848 117.526,26.081 117.526,23.8 v1(117.729,23.597)
  Bottom Layer w0.152: v1(117.729,23.597) 119.075,23.597 v1(119.634,23.038)
P0.22: SB15.1 SB25.1 U1.AD18 | length 12
  Top Layer w0.152: U1.AD18@116.414,34.367 116.414,34.03 117.096,33.347 117.096,31.359 119.411,29.045 119.411,25.674 119.634,25.451 119.634,24.308
  Top Layer w0.203: SB15.1@119.337,24.308 119.634,24.308 SB25.1@119.957,24.308
P0.23: SB10.1 SB20.1 U1.AC19 | length 30.3
  Top Layer w0.152: v1(104.445,23.47) 104.445,24.434 107.29,27.28 117.14,27.28 117.478,27.617 118.509,27.617 v2(118.694,27.432)
  Top Layer w0.203: SB20.1@107.881,23.038 v1(108.204,23.038) SB10.1@108.501,23.038
  Mid-Layer 1 w0.152: v2(116.664,34.867) 116.664,34.8 116.998,34.465 117.329,34.465 118.855,32.939 118.855,31.325 119.509,30.671 119.509,28.688 118.694,27.872 v2(118.694,27.432)
  Bottom Layer w0.152: v1(104.445,23.47) 105.225,23.47 105.656,23.038 v1(108.204,23.038)
P0.24: P24.14 SW3.2 U1.AD20 | length 103.7
  Top Layer w0.152: v1(89.586,30.505) 89.586,35.585 90.805,36.805 94.92,36.805 96.215,38.1 P24.14@97.472,38.1 ; v1(98.806,14.859) 100.37,13.295 100.37,7.72 101.588,6.502 SW3.2@102.278,6.502 SW3.2@109.028,6.502 109.691,6.502 111.328,4.864 120.548,4.864 121.99,6.305 121.99,24.503 120.221,26.272 120.221,28.663 117.401,31.482 117.401,33.473 116.914,33.961 U1.AD20@116.914,34.367
  Mid-Layer 2 w0.152: v1(98.806,14.859) 98.806,15.447 97.29,16.963 97.29,21.394 98.73,22.834 98.73,26.71 98.977,26.957 98.98,26.957 100.404,28.38 100.404,29.319 100.101,29.621 v1(100.101,30.048)
  Bottom Layer w0.152: v1(89.586,30.505) 89.941,30.505 90.627,29.82 94.871,29.82 95.328,30.277 98.948,30.277 99.177,30.048 v1(100.101,30.048)
P0.25: P24.15 SW4.2 U1.AC21 | length 95
  Top Layer w0.152: v1(89.916,29.743) 90.119,29.947 90.119,30.726 89.891,30.955 89.891,33.706 91.745,35.56 P24.15@93.027,35.56 ; v1(99.568,15.113) 100.675,14.006 100.675,7.846 101.09,7.43 110.921,7.43 111.85,6.502 SW4.2@112.54,6.502 SW4.2@119.29,6.502 120.137,6.502 121.685,8.049 121.685,24.38 119.918,26.147 119.918,28.316 v2(119.812,28.423) ; v2@119.812,28.448 v2@119.825,28.435
  Mid-Layer 1 w0.152: v2(117.164,34.867) 117.355,34.867 119.158,33.065 119.158,31.45 119.812,30.796 v2(119.812,28.423)
  Mid-Layer 2 w0.152: v1(99.568,15.113) 97.595,17.086 97.595,21.268 99.035,22.708 99.035,26.584 100.711,28.26 100.711,29.642 v1(100.813,29.743)
  Bottom Layer w0.152: v1(89.916,29.743) 90.145,29.515 94.997,29.515 95.455,29.972 98.822,29.972 99.279,29.515 100.584,29.515 v1(100.813,29.743)
P0.26: C51.2 R1.2 U1.G1 | length 11.4
  Top Layer w0.15: 109.55,36.551 109.674,36.551 109.675,36.552 111.244,38.12 111.244,38.214
  Top Layer w0.152: R1.2@104.318,37.66 C51.2@104.318,38.616 104.716,38.616 104.953,38.379 104.953,36.779 105.181,36.551 109.55,36.551 ; 111.244,38.214 111.244,38.32 111.791,38.867 U1.G1@111.914,38.867
P0.27: C52.1 R2.2 U1.H2 | length 13.4
  Top Layer w0.152: v2(102.692,38.608) 102.7,38.616 C52.1@103.403,38.616 R2.2@103.403,37.66
  Mid-Layer 1 w0.152: v2(102.692,38.608) 102.692,38.1 104.242,36.551 109.674,36.551 111.741,38.617 v2@112.378,38.617
  other v2: 112.414,38.617
P0.28/AIN4: P2.3 P8.3 P14.6 TP44.1 U1.B11 | length 107.5
  Top Layer w0.152: v1(96.774,23.012) 96.774,23.354 97.285,23.865 97.285,25.276 TP44.1@97.79,25.781
  Top Layer w0.381: P14.6@55.88,3.81 P2.3@55.88,6.155 v1(55.88,7.62) P2.3@55.88,9.085
  Mid-Layer 1 w0.152: v1(102.743,47.607) 103.089,47.953 113.466,47.953 113.665,47.754 113.665,46.598 113.767,46.496 113.767,43.993 114.151,43.608 114.151,41.579 114.664,41.067 v2(114.664,40.367)
  Mid-Layer 2 w0.152: v1(55.88,7.62) 57.023,8.763 63.973,8.763 64.289,8.448 69.164,8.448 72.273,11.557 88.824,11.557 96.071,18.804 96.071,22.31 v1(96.774,23.012) 96.915,23.153 96.915,23.728 97.506,24.319 97.506,24.887 97.511,24.892 97.511,27.215 98.273,27.977 98.273,30.279 102.768,34.775 102.768,45.009 102.187,45.59 102.187,47.052 v1(102.743,47.607)
  Bottom Layer w0.381: P8.3@55.88,6.155 v1(55.88,7.62) P8.3@55.88,9.085
P0.29/AIN5: P2.4 P8.4 P14.8 TP45.1 U1.A10 | length 106.1
  Top Layer w0.152: v1(97.485,23.317) 98.73,24.562 98.73,26.746 TP45.1@97.79,27.686 ; v2(113.233,47.549) 113.233,46.445 114.397,45.281 114.397,40.884 U1.A10@114.414,40.867 ; v2@113.309,47.549 v2@113.309,47.574
  Top Layer w0.381: P14.8@58.42,3.81 P2.4@58.42,6.155 v1(58.42,7.62) P2.4@58.42,9.085
  Mid-Layer 1 w0.152: v1(102.743,46.845) 103.472,47.574 v2@113.233,47.574
  Mid-Layer 2 w0.152: v1(58.42,7.62) 59.258,8.458 63.847,8.458 64.162,8.143 69.29,8.143 72.399,11.252 88.95,11.252 96.376,18.678 96.376,21.773 97.305,22.702 97.305,23.137 v1(97.485,23.317) 97.815,23.647 97.815,27.089 98.577,27.851 98.577,30.153 102.54,34.115 102.54,34.119 103.099,34.677 103.099,45.136 102.54,45.695 102.54,46.642 v1(102.743,46.845)
  Bottom Layer w0.381: P8.4@58.42,6.155 v1(58.42,7.62) P8.4@58.42,9.652
P0.30/AIN6: P2.5 P8.5 P14.10 TP46.1 U1.B9 | length 101.4
  Top Layer w0.152: v1(99.111,28.829) 98.73,28.448 98.73,27.305 99.695,26.34 TP46.1@99.695,25.781
  Top Layer w0.381: P14.10@60.96,3.81 P2.5@60.96,6.155 v1(60.96,7.62) P2.5@60.96,9.085
  Mid-Layer 1 w0.152: v1(103.505,46.744) 104.033,47.272 112.56,47.272 113.462,46.37 113.462,43.867 113.846,43.482 113.846,41.399 114.164,41.081 v2(114.164,40.367)
  Mid-Layer 2 w0.152: v1(60.96,7.62) 61.493,8.153 63.721,8.153 64.036,7.838 69.417,7.838 72.526,10.947 89.154,10.947 96.681,18.474 96.681,21.647 98.12,23.086 98.12,26.962 99.111,27.953 v1(99.111,28.829) 99.111,30.255 103.425,34.569 103.425,45.267 102.972,45.72 102.972,46.301 103.541,46.871 v1@103.657,46.871
  Bottom Layer w0.381: P8.5@60.96,6.155 v1(60.96,7.62) P8.5@60.96,9.652
P0.31/AIN7: SB17.1 SB29.1 U1.A8 | length 32.1
  Top Layer w0.152: v2(111.244,46.445) 112.802,46.445 114.092,45.155 114.092,41.256 113.914,41.077 U1.A8@113.914,40.867
  Top Layer w0.203: SB17.1@101.6,30.885 101.6,31.06 v1(101.6,31.449)
  Mid-Layer 1 w0.152: v1@103.657,46.109 104.486,46.937 110.16,46.937 110.651,46.445 v2(111.244,46.445)
  Mid-Layer 2 w0.152: v1(101.6,31.449) 101.6,32.313 102.868,33.581 102.868,33.584 103.734,34.45 103.734,45.753 v1(103.505,45.982) ; v1@103.454,46.032 v1@103.53,46.109 ; v1@103.594,46.045 v1@103.657,46.109
P1.00: P18.6 P24.16 P25.6 P25.14 SB57.1 U1.AD22 | length 107
  Top Layer w0.152: v1(56.845,18.44) 57.15,18.136 57.222,18.136 SB57.1@57.396,18.136 ; v1(61.733,25.694) 62.498,25.694 63.552,24.64 76.75,24.64 76.837,24.554 81.932,24.554 82.55,25.171 P18.6@82.55,25.99 82.55,26.773 83.159,27.381 83.159,32.843 82.55,33.452 P25.6@82.55,34.245 82.55,36.119 81.952,36.716 78.042,36.716 77.47,36.144 P25.14@77.47,34.245 ; v1(96.241,36.957) 97.472,35.725 P24.16@97.472,35.598 ; U1.AD22@117.414,34.367 117.414,33.892 117.704,33.602 117.704,31.607 119.618,29.693 v1(120.752,29.693)
  Mid-Layer 2 w0.152: v1(96.215,28.829) 95.987,29.058 95.987,36.703 v1(96.241,36.957)
  Bottom Layer w0.152: v1(56.845,18.44) 56.845,19.837 61.738,24.73 61.738,25.689 v1(61.733,25.694) ; v1(83.337,27.686) 83.768,27.254 86.182,27.254 87.528,28.6 95.987,28.6 v1(96.215,28.829) 96.444,28.6 97.179,28.6 98.2,27.58 106.02,27.58 106.022,27.582 110.54,27.582 111.383,28.425 118.464,28.425 119.731,29.693 v1(120.752,29.693)
P1.01: P3.1 P9.1 P15.2 U1.Y23 | length 99.5
  Top Layer w0.152: P3.1@63.5,54.415 63.5,53.899 64.313,53.086 82.493,53.086 89.281,46.298 89.281,31.013 89.052,30.785 89.052,28.296 v1(89.281,28.067)
  Top Layer w0.381: P3.1@63.5,54.415 v1(63.5,55.88) P3.1@63.5,57.345 P15.2@63.5,59.69
  Mid-Layer 1 w0.152: v2(117.914,35.617) 118.154,35.617 122.58,31.191 122.58,29.718 122.022,29.159 v1(121.31,29.159)
  Bottom Layer w0.152: v1(89.281,28.067) 89.51,28.296 97.056,28.296 98.074,27.277 107.694,27.277 107.696,27.28 110.665,27.28 111.509,28.123 118.589,28.123 119.625,29.159 v1(121.31,29.159)
  Bottom Layer w0.381: P9.1@63.5,53.807 v1(63.5,55.88) P9.1@63.5,57.345
P1.02: P3.2 P9.2 P15.4 U1.W24 | length 102.5
  Top Layer w0.152: P3.2@60.96,54.415 60.96,53.797 61.976,52.781 82.367,52.781 88.976,46.172 88.976,31.14 88.748,30.911 88.748,27.584 v1(88.976,27.356) ; U1.W24@118.414,35.867 118.431,35.867 118.78,35.519 118.78,35.515 122.479,31.816 122.479,29.235 121.869,28.626 v1(120.752,28.626)
  Top Layer w0.381: P3.2@60.96,54.415 v1(60.96,55.88) P3.2@60.96,57.345 P15.4@60.96,59.69
  Bottom Layer w0.152: v1(88.976,27.356) 89.324,27.356 89.959,27.991 96.933,27.991 97.949,26.975 110.788,26.975 111.634,27.821 118.714,27.821 119.519,28.626 v1(120.752,28.626)
  Bottom Layer w0.381: P9.2@60.96,54.415 v1(60.96,55.88) P9.2@60.96,57.345
P1.03: P3.3 P9.3 P15.6 U1.V23 | length 107.4
  Top Layer w0.152: P3.3@58.42,54.415 58.42,53.823 59.766,52.476 82.241,52.476 88.671,46.046 88.671,31.266 88.443,31.037 88.443,26.873 v1(88.671,26.645)
  Top Layer w0.381: P3.3@58.42,54.415 v1(58.42,55.88) P3.3@58.42,57.345 P15.6@58.42,59.69
  Mid-Layer 1 w0.152: v2(117.914,36.117) 118.085,36.117 122.885,31.317 122.885,28.575 122.403,28.092 v1(121.31,28.092)
  Bottom Layer w0.152: v1(88.671,26.645) 89.052,26.645 90.094,27.686 96.81,27.686 97.826,26.67 110.911,26.67 111.759,27.518 118.839,27.518 119.414,28.092 v1(121.31,28.092)
  Bottom Layer w0.381: P9.3@58.42,54.415 v1(58.42,55.88) P9.3@58.42,57.345
P1.04: P3.4 P9.4 P15.8 U1.U24 | length 111
  Top Layer w0.152: P3.4@55.88,54.415 55.88,53.823 57.531,52.172 82.114,52.172 87.956,46.33 88.367,45.919 88.367,31.392 88.138,31.164 88.138,26.162 v1(88.367,25.933) ; U1.U24@118.414,36.367 118.414,36.307 118.487,36.233 118.565,36.233 119.084,35.714 119.084,35.641 122.783,31.942 122.783,28.041 122.301,27.559 v1(120.752,27.559)
  Top Layer w0.381: P3.4@55.88,54.415 v1(55.88,55.88) P3.4@55.88,57.345 P15.8@55.88,59.69
  Bottom Layer w0.152: v1(88.367,25.933) 88.773,25.933 90.221,27.381 96.687,27.381 97.703,26.365 111.034,26.365 111.885,27.216 118.965,27.216 119.308,27.559 v1(120.752,27.559)
  Bottom Layer w0.381: P9.4@55.88,54.415 v1(55.88,55.88) P9.4@55.88,57.345
P1.05: P3.5 P9.5 P15.10 U1.T23 | length 115.8
  Top Layer w0.152: P3.5@53.34,54.415 53.34,53.823 55.296,51.867 81.988,51.867 88.062,45.793 88.062,31.518 87.833,31.29 87.833,31.013 87.833,26.848 87.833,25.451 v1(88.062,25.222)
  Top Layer w0.381: P3.5@53.34,54.415 v1(53.34,55.88) P3.5@53.34,57.345 P15.10@53.34,59.69
  Mid-Layer 1 w0.152: v2(117.914,36.617) 118.016,36.617 119.684,34.95 119.686,34.95 122.072,32.564 122.072,32.561 123.19,31.444 123.19,27.635 122.58,27.026 v1(121.31,27.026)
  Bottom Layer w0.152: v1(88.062,25.222) 88.493,25.222 90.347,27.076 96.564,27.076 97.58,26.06 111.157,26.06 112.01,26.913 119.09,26.913 119.202,27.026 v1(121.31,27.026)
  Bottom Layer w0.381: P9.5@53.34,54.415 v1(53.34,55.88) P9.5@53.34,57.345
P1.06: P3.6 P9.6 P15.12 U1.R24 | length 119.5
  Top Layer w0.152: P3.6@50.8,54.415 50.8,53.823 53.061,51.562 81.862,51.562 87.757,45.667 87.757,31.645 87.528,31.416 87.528,31.14 87.528,31.115 87.528,26.822 87.528,24.74 v1(87.757,24.511) ; U1.R24@118.414,36.867 118.431,36.867 119.389,35.909 119.389,35.767 123.088,32.068 123.088,27.178 122.403,26.492 v1(120.752,26.492)
  Top Layer w0.381: P3.6@50.8,54.415 v1(50.8,55.88) P3.6@50.8,57.345 P15.12@50.8,59.69
  Bottom Layer w0.152: v1(87.757,24.511) 88.213,24.511 90.473,26.772 96.442,26.772 97.458,25.756 111.28,25.756 112.135,26.611 119.107,26.611 119.225,26.492 v1(120.752,26.492)
  Bottom Layer w0.381: P9.6@50.8,54.415 v1(50.8,55.88) P9.6@50.8,57.345
P1.07: P3.7 P9.7 P15.14 U1.P23 U8.3 | length 130.9
  Top Layer w0.152: P3.7@48.26,54.415 48.26,53.823 50.825,51.257 81.736,51.257 87.452,45.541 87.452,31.771 87.224,31.542 87.224,31.266 87.224,30.989 87.224,24.028 v1(87.452,23.8) ; U8.3@92.773,23.822 93.196,23.822 v2@93.294,23.724
  Top Layer w0.381: P3.7@48.26,54.415 v1(48.26,55.88) P3.7@48.26,57.345 P15.14@48.26,59.69
  Mid-Layer 1 w0.152: v1(87.452,23.8) 87.782,23.47 93.04,23.47 v2@93.294,23.724 ; v2(117.914,37.117) 117.984,37.117 118.515,36.587 118.515,36.552 122.415,32.652 ; v1(121.31,25.959) 122.352,25.959 123.495,27.102 123.495,31.57 122.415,32.649
  Bottom Layer w0.152: v1(87.452,23.8) 87.986,23.8 90.653,26.467 96.319,26.467 97.337,25.448 106.398,25.448 106.401,25.451 111.406,25.451 112.264,26.309 118.975,26.309 119.223,26.06 119.227,26.06 119.328,25.959 v1(121.31,25.959)
  Bottom Layer w0.381: P9.7@48.26,54.415 v1(48.26,55.88) P9.7@48.26,57.345
  other v2: 93.294,23.749
P1.08: SB16.1 SB26.1 SB61.1 U1.P2 | length 17.4
  Top Layer w0.152: SB61.1@101.951,42.879 101.951,42.526 SB26.1@101.951,41.555 SB16.1@101.951,40.231 101.951,37.19 v2(102.387,36.754)
  Mid-Layer 1 w0.152: v2(102.387,36.754) 103.505,35.636 110.053,35.636 111.534,37.117 v2(112.414,37.117)
P1.09: P24.17 P25.20 U1.R1 | length 51
  Top Layer w0.15: 110.058,35.331 110.203,35.331 111.739,36.867 U1.R1@111.914,36.867
  Top Layer w0.152: P25.20@73.66,33.401 P25.20@73.66,34.245 73.787,34.372 v1(73.787,35.865) ; P24.17@93.027,33.02 94.259,33.02 95.606,34.366 99.162,34.366 v1(99.847,35.052) 100.66,35.052 101.422,34.29 104.546,34.29 105.588,35.331 110.058,35.331
  Bottom Layer w0.152: v1@73.66,35.738 v1(73.787,35.865) 74.32,36.398 77.326,36.398 79.129,34.595 98.658,34.595 99.115,35.052 v1(99.847,35.052)
P1.10: P4.1 P10.1 P16.2 U1.A20 | length 94.7
  Top Layer w0.152: P4.1@41.656,54.415 41.656,53.823 42.393,53.086 47.213,53.086 49.651,50.648 80.061,50.648 v2(80.173,50.535) ; U1.A20@116.914,40.867 v2(116.914,41.351)
  Top Layer w0.381: P4.1@41.656,54.415 v1(41.656,55.88) P4.1@41.656,57.345 P16.2@41.656,59.69
  Mid-Layer 1 w0.152: v2(80.173,50.535) 80.217,50.579 81.994,50.579 82.179,50.394 114.499,50.394 116.327,48.565 116.327,46.229 115.311,45.213 115.311,44.603 115.675,44.24 115.675,42.211 116.534,41.351 v2(116.914,41.351)
  Bottom Layer w0.381: P10.1@41.656,54.415 v1(41.656,55.88) P10.1@41.656,57.345
P1.11: P4.2 P10.2 P16.4 U1.B19 | length 97.2
  Top Layer w0.152: P4.2@39.116,54.415 39.116,53.823 40.157,52.781 47.086,52.781 49.525,50.343 79.795,50.343 80.006,50.131 80.49,50.131 v2(80.533,50.175)
  Top Layer w0.381: P4.2@39.116,54.415 v1(39.116,55.88) P4.2@39.116,57.345 P16.4@39.116,59.69
  Mid-Layer 1 w0.152: v2(80.533,50.175) 80.577,50.219 81.922,50.219 82.052,50.089 114.372,50.089 116.023,48.439 116.023,46.356 115.007,45.34 115.007,44.477 115.37,44.113 115.37,42.084 116.664,40.791 v2(116.664,40.367)
  Bottom Layer w0.381: P10.2@39.116,54.415 v1(39.116,55.88) P10.2@39.116,57.345
P1.12: P4.3 P10.3 P16.6 U1.B17 | length 99.3
  Top Layer w0.152: P4.3@36.576,54.415 36.576,53.823 37.922,52.476 46.96,52.476 49.399,50.038 79.669,50.038 79.935,49.771 80.85,49.771 v2(80.893,49.815)
  Top Layer w0.381: P4.3@36.576,54.415 v1(36.576,55.88) P4.3@36.576,57.345 P16.6@36.576,59.69
  Mid-Layer 1 w0.152: v2(80.893,49.815) 80.937,49.859 81.851,49.859 81.926,49.784 114.246,49.784 115.718,48.312 115.718,46.482 114.702,45.466 114.702,44.351 115.065,43.987 115.065,41.958 116.164,40.86 v2(116.164,40.367)
  Bottom Layer w0.381: P10.3@36.576,54.415 v1(36.576,55.88) P10.3@36.576,57.345
P1.13: P4.4 P5.4 P10.4 P11.4 P16.8 U1.A16 | length 121
  Top Layer w0.152: P4.4@34.036,54.415 34.036,53.823 35.687,52.172 46.834,52.172 49.272,49.733 63.576,49.733 v1(65.1,48.209) 65.329,47.981 65.947,47.981 67.7,49.733 79.542,49.733 79.864,49.412 81.209,49.412 v2(81.253,49.455) ; v1(66.319,34.163) 66.319,33.82 P5.4@67.119,33.02 ; v2(115.291,47.701) 115.311,47.68 115.311,41.584 115.914,40.982 U1.A16@115.914,40.867
  Top Layer w0.381: P4.4@34.036,54.415 v1(34.036,55.88) P4.4@34.036,57.345 P16.8@34.036,59.69
  Mid-Layer 1 w0.152: v2(81.253,49.455) 81.297,49.499 81.78,49.499 81.8,49.479 114.12,49.479 115.316,48.283 115.316,47.727 v2(115.291,47.701)
  Mid-Layer 2 w0.152: v1(65.1,48.209) 65.093,48.209 63.312,46.429 63.312,37.402 66.319,34.394 v1(66.319,34.163)
  Bottom Layer w0.152: v1(66.319,34.163) 67.462,33.02 P11.4@67.722,33.02
  Bottom Layer w0.381: P10.4@34.036,54.415 v1(34.036,55.88) P10.4@34.036,57.345
P1.14: P4.5 P5.1 P10.5 P11.1 P16.10 U1.B15 | length 120.3
  Top Layer w0.152: P4.5@31.496,54.415 31.496,53.823 33.452,51.867 46.708,51.867 49.146,49.428 62.916,49.428 v1(64.237,48.108) 64.668,47.676 66.074,47.676 67.826,49.428 79.416,49.428 79.793,49.052 81.569,49.052 v2(81.613,49.095) ; P5.1@62.674,35.56 62.992,35.878 v1(62.992,36.754)
  Top Layer w0.381: P4.5@31.496,54.415 v1(31.496,55.88) P4.5@31.496,57.345 P16.10@31.496,59.69
  Mid-Layer 1 w0.152: v2(81.613,49.095) 81.692,49.174 113.994,49.174 114.884,48.284 114.884,47.537 115.252,47.169 115.252,46.447 114.397,45.592 114.397,44.225 114.761,43.861 114.761,41.832 115.664,40.929 v2(115.664,40.367)
  Mid-Layer 2 w0.152: v1(62.992,36.754) 63.007,36.769 63.007,46.878 v1(64.237,48.108)
  Bottom Layer w0.152: P11.1@61.473,35.56 P11.1@62.072,35.56 62.072,35.834 v1(62.992,36.754)
  Bottom Layer w0.381: P10.5@31.496,54.415 v1(31.496,55.88) P10.5@31.496,57.345
P1.15: P4.6 P5.3 P10.6 P11.3 P16.12 U1.A14 | length 123.4
  Top Layer w0.152: P4.6@28.956,54.415 28.956,53.823 31.217,51.562 46.581,51.562 49.02,49.124 62.205,49.124 v1(63.068,48.26) 63.957,47.371 66.2,47.371 67.952,49.124 79.29,49.124 79.722,48.692 81.929,48.692 v2(81.973,48.735) ; P5.3@62.674,33.02 62.992,33.338 v1(62.992,34.214) ; v2(114.783,46.787) 115.007,46.563 115.007,41.457 115.414,41.05 U1.A14@115.414,40.867
  Top Layer w0.381: P4.6@28.956,54.415 v1(28.956,55.88) P4.6@28.956,57.345 P16.12@28.956,59.69
  Mid-Layer 1 w0.152: v2(81.973,48.735) 82.107,48.87 113.867,48.87 114.579,48.158 114.579,47.012 v2@114.783,46.809
  Mid-Layer 2 w0.152: v1(62.992,34.214) 62.992,35.999 62.459,36.533 62.459,37.069 62.702,37.313 62.702,47.894 v1(63.068,48.26)
  Bottom Layer w0.152: P11.3@62.072,33.02 62.072,33.294 v1(62.992,34.214)
  Bottom Layer w0.381: P10.6@28.956,54.415 v1(28.956,55.88) P10.6@28.956,57.345
PB5: Q2.3 R23.2 U2.97 | length 36.7
  Top Layer w0.254: U2.97@36.179,20.9 38.553,20.9 41.783,24.13 41.783,30.048 v1(42.291,30.556) ; Q2.3@52.207,45.013 52.205,45.011 v1(52.205,43.205) 53.238,42.172 53.238,41.631 R23.2@53.297,41.631
  Bottom Layer w0.254: v1(42.291,30.556) 42.52,30.785 42.52,37.744 43.561,38.786 47.786,38.786 v1(52.205,43.205)
PB6: Q3.3 R27.2 U2.98 | length 72.9
  Top Layer w0.254: v1(8.56,54.508) 10.152,56.101 R27.2@10.287,56.101 11.862,57.676 11.862,58.536 11.587,58.812 10.397,58.812 Q3.3@10.319,58.734 ; U2.98@36.179,20.4 38.628,20.4 42.367,24.139 v1(42.367,29.616)
  Bottom Layer w0.254: v1(8.56,54.508) 9.007,54.508 14.951,48.565 37.394,48.565 37.516,48.443 37.516,40.31 40.386,37.44 40.386,36.893 40.335,36.842 40.335,36.043 40.462,35.916 40.462,31.267 42.113,29.616 v1(42.367,29.616)
PWM_IN: R11.1 SB61.2 | length 39.3
  Top Layer w0.152: SB61.2@101.326,42.879 101.326,43.232 v1(101.326,43.744) ; v2(120.823,59.5) R11.1@121.498,59.5
  Mid-Layer 1 w0.152: v1(98.679,57.353) 98.933,57.607 118.93,57.607 v2(120.823,59.5)
  Mid-Layer 2 w0.152: v1(98.679,57.353) 98.679,50.044 101.326,47.396 v1(101.326,43.744)
PWM_UCTRL: C98.1 R13.1 R14.2 R15.1 R16.2 TP49.1 U26.4 | length 15.7
  Top Layer w0.254: TP49.1@125.362,49.929 125.82,50.387 C98.1@126.691,50.387 126.698,50.394 R15.1@126.698,51.25 ; R16.2@125.829,51.25 R15.1@126.698,51.25 ; R15.1@126.716,51.25 R15.1@126.698,51.25 ; R13.1@129.999,59.5 R14.2@130.896,59.5 130.924,59.5 131.496,58.928 131.496,57.506 131.259,57.269 131.259,55.541 129.311,53.594 127.556,53.594 126.698,52.737 U26.4@126.698,52.542 R15.1@126.698,51.25
RF: C4.2 C22.1 L1.2 U9.21 | length 3.9
  Top Layer w0.3: L1.2@121.613,38.379 U9.21@125.503,38.379
SCL: P4.10 P10.10 P16.20 R2.1 U7.12 U10.D1 | length 170.7
  Top Layer w0.152: P4.10@18.796,54.415 18.796,53.823 21.971,50.648 46.203,50.648 48.641,48.209 61.442,48.209 63.194,46.457 66.579,46.457 68.331,48.209 78.911,48.209 79.508,47.612 83.009,47.612 v2(83.053,47.656) 84.044,47.656 86.538,45.162 86.538,37.998 86.081,37.541 86.081,34.883 86.309,34.654 86.309,23.47 85.852,23.012 82.448,23.012 81.267,21.831 81.267,21.044 81.34,20.971 U7.12@81.34,20.535 ; v1(99.847,38.252) 100.659,38.252 101.244,37.668 101.244,37.465 101.869,36.841 101.869,36.706 102.252,36.322 103.065,36.322 R2.1@103.403,36.66 ; v2(113.052,59.055) 113.052,59.455 U10.D1@113.097,59.5 U10.D1@113.103,59.494
  Top Layer w0.381: P4.10@18.796,54.415 v1(18.796,55.88) P4.10@18.796,57.345 P16.20@18.796,59.69
  Mid-Layer 1 w0.152: v2(83.053,47.656) 83.352,47.955 98.273,47.955 99.822,46.406 v1(99.847,46.406) ; v1(97.561,57.353) 97.561,57.582 98.196,58.217 112.214,58.217 v2(113.052,59.055)
  Mid-Layer 2 w0.152: v1(97.561,57.353) 97.561,55.956 96.545,54.94 96.545,49.682 99.822,46.406 v1(99.847,46.406) 99.746,46.304 99.746,38.354 v1(99.847,38.252)
  Bottom Layer w0.381: P10.10@18.796,54.415 v1(18.796,55.88) P10.10@18.796,57.345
